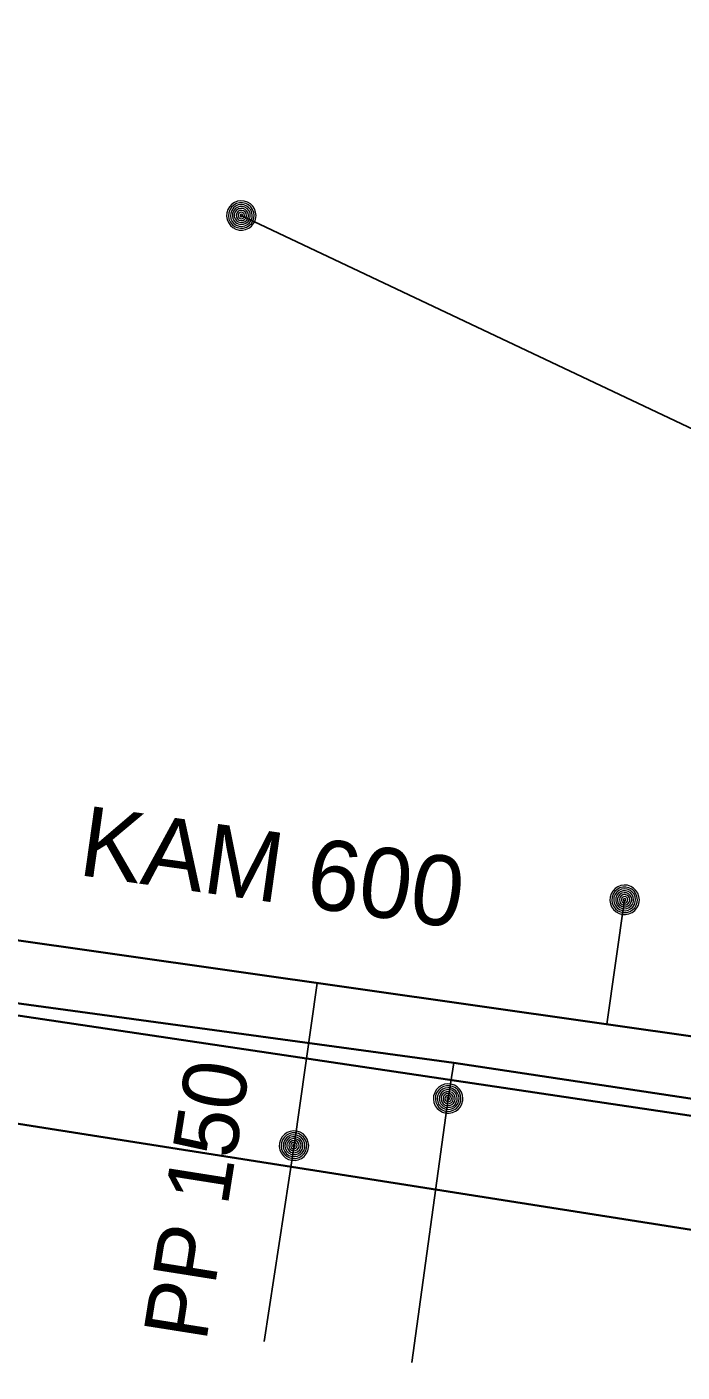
# Model space of a CAD drawing. Extents: x -866761 to -866592, y -1013996 to -1013877.
# Drawn here: x -866639.65 to -866629.36, y -1013979.36 to -1013958.25 of the extents above; entities that cross this region are included whole.
import ezdxf

# ---------------------------------------------------------------- set-up
doc = ezdxf.new("R2010")
doc.units = 0
doc.header["$LTSCALE"] = 0.44
for name, color, linetype, lineweight in [('1', 7, 'Continuous', 35), ('12', 7, 'Continuous', 13), ('21', 7, 'Continuous', 35), ('23', 7, 'Continuous', 25), ('25', 7, 'Continuous', 13), ('3', 7, 'Continuous', 25), ('32', 7, 'Continuous', 13)]:
    doc.layers.add(name, color=color, linetype=linetype, lineweight=lineweight)

msp = doc.modelspace()

# ---------------------------------------------------------------- linework, layer by layer
at = {"layer": '1'}
msp.add_line((-866612.967, -1013977.763), (-866734.931, -1013959.586), dxfattribs=at)
for points in [[(-866612.815, -1013977.108), (-866621.035, -1013976.325), (-866621.378, -1013976.297), (-866626.243, -1013975.519), (-866632.94, -1013974.51), (-866645.03, -1013972.86), (-866647.305, -1013972.501), (-866654.48, -1013971.31), (-866668.882, -1013969.171), (-866678.229, -1013967.78), (-866685.446, -1013966.718), (-866689.8, -1013966.06), (-866697.865, -1013964.927), (-866723.097, -1013961.352), (-866726.923, -1013960.77), (-866727.214, -1013960.734), (-866737.38, -1013959.64), (-866746.09, -1013958.48), (-866747.84, -1013958.25), (-866748.13, -1013958.99), (-866750.15, -1013958.69)], [(-866613.338, -1013979.363), (-866624.951, -1013977.802), (-866715.256, -1013963.593), (-866735.102, -1013960.577)]]:
    msp.add_lwpolyline(points, dxfattribs=at)
at = {"layer": '12'}
for points in [[(-866632.799, -1013975.07), (-866632.805, -1013975.018), (-866632.822, -1013974.968), (-866632.851, -1013974.924), (-866632.888, -1013974.887), (-866632.933, -1013974.86), (-866632.983, -1013974.843), (-866633.036, -1013974.839), (-866633.088, -1013974.846), (-866633.137, -1013974.865), (-866633.18, -1013974.894), (-866633.216, -1013974.933), (-866633.242, -1013974.978), (-866633.258, -1013975.029), (-866633.261, -1013975.081), (-866633.253, -1013975.133), (-866633.233, -1013975.182), (-866633.202, -1013975.225), (-866633.163, -1013975.259), (-866633.117, -1013975.285), (-866633.066, -1013975.299), (-866633.013, -1013975.301), (-866632.962, -1013975.291), (-866632.914, -1013975.27), (-866632.871, -1013975.239), (-866632.837, -1013975.198), (-866632.813, -1013975.152), (-866632.801, -1013975.101)], [(-866632.829, -1013975.07), (-866632.835, -1013975.021), (-866632.852, -1013974.975), (-866632.88, -1013974.935), (-866632.917, -1013974.903), (-866632.961, -1013974.881), (-866633.009, -1013974.87), (-866633.058, -1013974.87), (-866633.105, -1013974.883), (-866633.148, -1013974.907), (-866633.184, -1013974.94), (-866633.211, -1013974.981), (-866633.227, -1013975.028), (-866633.231, -1013975.077), (-866633.224, -1013975.125), (-866633.205, -1013975.17), (-866633.175, -1013975.21), (-866633.137, -1013975.241), (-866633.093, -1013975.261), (-866633.045, -1013975.271), (-866632.996, -1013975.269), (-866632.949, -1013975.254), (-866632.906, -1013975.229), (-866632.872, -1013975.195), (-866632.846, -1013975.153), (-866632.832, -1013975.106)], [(-866632.859, -1013975.07), (-866632.865, -1013975.025), (-866632.882, -1013974.983), (-866632.91, -1013974.948), (-866632.946, -1013974.921), (-866632.988, -1013974.904), (-866633.033, -1013974.899), (-866633.078, -1013974.905), (-866633.119, -1013974.924), (-866633.154, -1013974.952), (-866633.181, -1013974.989), (-866633.197, -1013975.031), (-866633.201, -1013975.076), (-866633.194, -1013975.121), (-866633.175, -1013975.162), (-866633.146, -1013975.196), (-866633.109, -1013975.222), (-866633.066, -1013975.238), (-866633.021, -1013975.241), (-866632.976, -1013975.233), (-866632.936, -1013975.213), (-866632.902, -1013975.184), (-866632.876, -1013975.146), (-866632.862, -1013975.103)], [(-866632.889, -1013975.07), (-866632.894, -1013975.029), (-866632.912, -1013974.992), (-866632.939, -1013974.961), (-866632.974, -1013974.94), (-866633.014, -1013974.929), (-866633.055, -1013974.931), (-866633.094, -1013974.944), (-866633.128, -1013974.968), (-866633.153, -1013975), (-866633.168, -1013975.038), (-866633.171, -1013975.079), (-866633.163, -1013975.119), (-866633.143, -1013975.155), (-866633.114, -1013975.184), (-866633.077, -1013975.203), (-866633.037, -1013975.211), (-866632.996, -1013975.207), (-866632.958, -1013975.192), (-866632.926, -1013975.166), (-866632.903, -1013975.132), (-866632.89, -1013975.093)], [(-866632.919, -1013975.07), (-866632.924, -1013975.034), (-866632.942, -1013975.002), (-866632.968, -1013974.977), (-866633.002, -1013974.962), (-866633.038, -1013974.959), (-866633.073, -1013974.967), (-866633.104, -1013974.987), (-866633.127, -1013975.015), (-866633.14, -1013975.049), (-866633.14, -1013975.086), (-866633.129, -1013975.121), (-866633.108, -1013975.15), (-866633.078, -1013975.171), (-866633.043, -1013975.181), (-866633.006, -1013975.179), (-866632.972, -1013975.165), (-866632.945, -1013975.142), (-866632.926, -1013975.11), (-866632.919, -1013975.075)], [(-866632.949, -1013975.07), (-866632.954, -1013975.039), (-866632.971, -1013975.013), (-866632.997, -1013974.996), (-866633.027, -1013974.989), (-866633.058, -1013974.993), (-866633.085, -1013975.01), (-866633.103, -1013975.034), (-866633.111, -1013975.065), (-866633.107, -1013975.095), (-866633.092, -1013975.123), (-866633.068, -1013975.142), (-866633.038, -1013975.151), (-866633.007, -1013975.148), (-866632.979, -1013975.134), (-866632.959, -1013975.11), (-866632.949, -1013975.081)], [(-866632.979, -1013975.07), (-866632.984, -1013975.046), (-866633.001, -1013975.028), (-866633.024, -1013975.019), (-866633.048, -1013975.022), (-866633.069, -1013975.036), (-866633.08, -1013975.058), (-866633.08, -1013975.083), (-866633.068, -1013975.104), (-866633.048, -1013975.118), (-866633.023, -1013975.121), (-866633, -1013975.112), (-866632.984, -1013975.094)], [(-866633.009, -1013975.07), (-866633.014, -1013975.055), (-866633.029, -1013975.049), (-866633.044, -1013975.053), (-866633.051, -1013975.067), (-866633.047, -1013975.082), (-866633.034, -1013975.091), (-866633.019, -1013975.088), (-866633.009, -1013975.076)]]:
    msp.add_lwpolyline(points, close=True, dxfattribs=at)
at = {"layer": '21'}
msp.add_line((-866647.459, -1013971.5), (-866622.959, -1013974.98), dxfattribs=at)
at = {"layer": '23'}
for p, q in [((-866636.279, -1013961.21), (-866624.162, -1013966.944)), ((-866630.538, -1013973.904), (-866630.259, -1013971.95))]:
    msp.add_line(p, q, dxfattribs=at)
msp.add_lwpolyline([(-866635.087, -1013973.257), (-866635.449, -1013975.804), (-866635.918, -1013978.885)], dxfattribs=at)
at = {"layer": '25'}
for points in [[(-866636.048, -1013961.21), (-866636.054, -1013961.158), (-866636.071, -1013961.108), (-866636.1, -1013961.064), (-866636.137, -1013961.027), (-866636.182, -1013961), (-866636.232, -1013960.983), (-866636.285, -1013960.979), (-866636.337, -1013960.986), (-866636.386, -1013961.005), (-866636.429, -1013961.034), (-866636.465, -1013961.073), (-866636.491, -1013961.118), (-866636.507, -1013961.169), (-866636.51, -1013961.221), (-866636.502, -1013961.273), (-866636.482, -1013961.322), (-866636.451, -1013961.365), (-866636.412, -1013961.399), (-866636.366, -1013961.425), (-866636.315, -1013961.439), (-866636.262, -1013961.441), (-866636.211, -1013961.431), (-866636.163, -1013961.41), (-866636.12, -1013961.379), (-866636.086, -1013961.338), (-866636.062, -1013961.292), (-866636.049, -1013961.241)], [(-866636.078, -1013961.21), (-866636.084, -1013961.161), (-866636.101, -1013961.115), (-866636.129, -1013961.075), (-866636.166, -1013961.043), (-866636.21, -1013961.021), (-866636.258, -1013961.01), (-866636.307, -1013961.01), (-866636.353, -1013961.023), (-866636.397, -1013961.047), (-866636.433, -1013961.08), (-866636.46, -1013961.121), (-866636.476, -1013961.168), (-866636.48, -1013961.217), (-866636.473, -1013961.265), (-866636.454, -1013961.31), (-866636.424, -1013961.35), (-866636.386, -1013961.381), (-866636.342, -1013961.401), (-866636.294, -1013961.411), (-866636.245, -1013961.409), (-866636.198, -1013961.394), (-866636.155, -1013961.369), (-866636.12, -1013961.335), (-866636.095, -1013961.293), (-866636.081, -1013961.246)], [(-866636.108, -1013961.21), (-866636.114, -1013961.165), (-866636.13, -1013961.123), (-866636.159, -1013961.088), (-866636.195, -1013961.061), (-866636.237, -1013961.044), (-866636.282, -1013961.039), (-866636.326, -1013961.045), (-866636.368, -1013961.064), (-866636.402, -1013961.092), (-866636.429, -1013961.129), (-866636.446, -1013961.171), (-866636.45, -1013961.216), (-866636.443, -1013961.261), (-866636.424, -1013961.302), (-866636.395, -1013961.336), (-866636.358, -1013961.362), (-866636.315, -1013961.378), (-866636.27, -1013961.381), (-866636.225, -1013961.373), (-866636.184, -1013961.353), (-866636.151, -1013961.324), (-866636.125, -1013961.286), (-866636.111, -1013961.243)], [(-866636.138, -1013961.21), (-866636.142, -1013961.169), (-866636.161, -1013961.132), (-866636.188, -1013961.101), (-866636.223, -1013961.08), (-866636.263, -1013961.069), (-866636.304, -1013961.071), (-866636.343, -1013961.084), (-866636.377, -1013961.108), (-866636.402, -1013961.14), (-866636.417, -1013961.178), (-866636.419, -1013961.219), (-866636.412, -1013961.259), (-866636.392, -1013961.295), (-866636.363, -1013961.324), (-866636.326, -1013961.343), (-866636.286, -1013961.351), (-866636.245, -1013961.347), (-866636.206, -1013961.332), (-866636.174, -1013961.306), (-866636.152, -1013961.272), (-866636.139, -1013961.233)], [(-866636.168, -1013961.21), (-866636.173, -1013961.174), (-866636.191, -1013961.142), (-866636.217, -1013961.117), (-866636.25, -1013961.102), (-866636.287, -1013961.099), (-866636.321, -1013961.107), (-866636.353, -1013961.127), (-866636.375, -1013961.155), (-866636.389, -1013961.189), (-866636.389, -1013961.226), (-866636.378, -1013961.261), (-866636.357, -1013961.29), (-866636.326, -1013961.311), (-866636.292, -1013961.321), (-866636.255, -1013961.319), (-866636.221, -1013961.305), (-866636.194, -1013961.282), (-866636.174, -1013961.25), (-866636.168, -1013961.215)], [(-866636.198, -1013961.21), (-866636.203, -1013961.179), (-866636.22, -1013961.153), (-866636.245, -1013961.136), (-866636.276, -1013961.129), (-866636.307, -1013961.133), (-866636.334, -1013961.15), (-866636.352, -1013961.174), (-866636.36, -1013961.205), (-866636.356, -1013961.235), (-866636.341, -1013961.263), (-866636.316, -1013961.282), (-866636.287, -1013961.291), (-866636.255, -1013961.288), (-866636.228, -1013961.274), (-866636.208, -1013961.25), (-866636.198, -1013961.221)], [(-866636.228, -1013961.21), (-866636.233, -1013961.186), (-866636.25, -1013961.168), (-866636.272, -1013961.159), (-866636.297, -1013961.162), (-866636.318, -1013961.176), (-866636.329, -1013961.198), (-866636.329, -1013961.223), (-866636.316, -1013961.244), (-866636.297, -1013961.258), (-866636.272, -1013961.261), (-866636.249, -1013961.252), (-866636.233, -1013961.234)], [(-866636.258, -1013961.21), (-866636.263, -1013961.195), (-866636.277, -1013961.189), (-866636.293, -1013961.193), (-866636.299, -1013961.207), (-866636.296, -1013961.222), (-866636.282, -1013961.231), (-866636.267, -1013961.228), (-866636.258, -1013961.216)], [(-866630.027, -1013971.95), (-866630.034, -1013971.898), (-866630.051, -1013971.848), (-866630.08, -1013971.804), (-866630.117, -1013971.767), (-866630.162, -1013971.74), (-866630.212, -1013971.723), (-866630.265, -1013971.719), (-866630.316, -1013971.726), (-866630.365, -1013971.745), (-866630.409, -1013971.774), (-866630.445, -1013971.813), (-866630.471, -1013971.858), (-866630.487, -1013971.909), (-866630.49, -1013971.961), (-866630.482, -1013972.013), (-866630.462, -1013972.062), (-866630.431, -1013972.105), (-866630.392, -1013972.139), (-866630.346, -1013972.165), (-866630.294, -1013972.179), (-866630.242, -1013972.181), (-866630.191, -1013972.171), (-866630.142, -1013972.15), (-866630.1, -1013972.119), (-866630.066, -1013972.078), (-866630.042, -1013972.032), (-866630.029, -1013971.981)], [(-866630.058, -1013971.95), (-866630.064, -1013971.901), (-866630.081, -1013971.855), (-866630.108, -1013971.815), (-866630.146, -1013971.783), (-866630.19, -1013971.761), (-866630.238, -1013971.75), (-866630.287, -1013971.75), (-866630.333, -1013971.763), (-866630.377, -1013971.787), (-866630.413, -1013971.82), (-866630.44, -1013971.861), (-866630.456, -1013971.908), (-866630.46, -1013971.957), (-866630.453, -1013972.005), (-866630.434, -1013972.05), (-866630.404, -1013972.09), (-866630.365, -1013972.121), (-866630.321, -1013972.141), (-866630.274, -1013972.151), (-866630.225, -1013972.149), (-866630.178, -1013972.134), (-866630.135, -1013972.109), (-866630.1, -1013972.075), (-866630.075, -1013972.033), (-866630.061, -1013971.986)], [(-866630.088, -1013971.95), (-866630.093, -1013971.905), (-866630.11, -1013971.863), (-866630.139, -1013971.828), (-866630.174, -1013971.801), (-866630.217, -1013971.784), (-866630.262, -1013971.779), (-866630.306, -1013971.785), (-866630.348, -1013971.804), (-866630.382, -1013971.832), (-866630.409, -1013971.869), (-866630.426, -1013971.911), (-866630.429, -1013971.956), (-866630.423, -1013972.001), (-866630.404, -1013972.042), (-866630.375, -1013972.076), (-866630.338, -1013972.102), (-866630.294, -1013972.118), (-866630.25, -1013972.121), (-866630.205, -1013972.113), (-866630.164, -1013972.093), (-866630.13, -1013972.064), (-866630.105, -1013972.026), (-866630.091, -1013971.983)], [(-866630.118, -1013971.95), (-866630.122, -1013971.909), (-866630.141, -1013971.872), (-866630.168, -1013971.841), (-866630.203, -1013971.82), (-866630.243, -1013971.809), (-866630.284, -1013971.811), (-866630.323, -1013971.824), (-866630.357, -1013971.848), (-866630.382, -1013971.88), (-866630.397, -1013971.918), (-866630.399, -1013971.959), (-866630.392, -1013971.999), (-866630.372, -1013972.035), (-866630.343, -1013972.064), (-866630.306, -1013972.083), (-866630.266, -1013972.091), (-866630.225, -1013972.087), (-866630.186, -1013972.072), (-866630.154, -1013972.046), (-866630.132, -1013972.012), (-866630.119, -1013971.973)], [(-866630.147, -1013971.95), (-866630.152, -1013971.914), (-866630.171, -1013971.882), (-866630.196, -1013971.857), (-866630.23, -1013971.842), (-866630.267, -1013971.839), (-866630.301, -1013971.847), (-866630.333, -1013971.867), (-866630.355, -1013971.895), (-866630.369, -1013971.929), (-866630.369, -1013971.966), (-866630.358, -1013972.001), (-866630.337, -1013972.03), (-866630.306, -1013972.051), (-866630.272, -1013972.061), (-866630.235, -1013972.059), (-866630.201, -1013972.045), (-866630.174, -1013972.022), (-866630.154, -1013971.99), (-866630.147, -1013971.955)], [(-866630.178, -1013971.95), (-866630.183, -1013971.919), (-866630.2, -1013971.893), (-866630.225, -1013971.876), (-866630.255, -1013971.869), (-866630.287, -1013971.873), (-866630.314, -1013971.89), (-866630.331, -1013971.914), (-866630.34, -1013971.945), (-866630.336, -1013971.975), (-866630.321, -1013972.003), (-866630.296, -1013972.022), (-866630.267, -1013972.031), (-866630.235, -1013972.028), (-866630.208, -1013972.014), (-866630.188, -1013971.99), (-866630.178, -1013971.961)], [(-866630.208, -1013971.95), (-866630.213, -1013971.926), (-866630.23, -1013971.908), (-866630.252, -1013971.899), (-866630.277, -1013971.902), (-866630.298, -1013971.916), (-866630.309, -1013971.938), (-866630.309, -1013971.963), (-866630.296, -1013971.984), (-866630.277, -1013971.998), (-866630.252, -1013972.001), (-866630.228, -1013971.992), (-866630.213, -1013971.974)], [(-866630.238, -1013971.95), (-866630.243, -1013971.935), (-866630.257, -1013971.929), (-866630.272, -1013971.933), (-866630.279, -1013971.947), (-866630.276, -1013971.962), (-866630.262, -1013971.971), (-866630.247, -1013971.968), (-866630.238, -1013971.956)]]:
    msp.add_lwpolyline(points, close=True, dxfattribs=at)
at = {"layer": '3'}
msp.add_lwpolyline([(-866632.94, -1013974.51), (-866633.03, -1013975.07), (-866633.599, -1013979.21)], dxfattribs=at)
at = {"layer": '32'}
for points in [[(-866635.221, -1013975.809), (-866635.227, -1013975.757), (-866635.244, -1013975.707), (-866635.273, -1013975.663), (-866635.31, -1013975.626), (-866635.355, -1013975.599), (-866635.405, -1013975.582), (-866635.458, -1013975.578), (-866635.51, -1013975.585), (-866635.559, -1013975.604), (-866635.602, -1013975.633), (-866635.638, -1013975.672), (-866635.664, -1013975.717), (-866635.68, -1013975.768), (-866635.683, -1013975.82), (-866635.675, -1013975.872), (-866635.655, -1013975.921), (-866635.624, -1013975.964), (-866635.585, -1013975.998), (-866635.539, -1013976.024), (-866635.488, -1013976.038), (-866635.435, -1013976.04), (-866635.384, -1013976.03), (-866635.336, -1013976.009), (-866635.293, -1013975.978), (-866635.259, -1013975.937), (-866635.235, -1013975.891), (-866635.223, -1013975.84)], [(-866635.251, -1013975.809), (-866635.257, -1013975.76), (-866635.274, -1013975.714), (-866635.302, -1013975.674), (-866635.339, -1013975.642), (-866635.383, -1013975.62), (-866635.431, -1013975.609), (-866635.48, -1013975.609), (-866635.527, -1013975.622), (-866635.57, -1013975.646), (-866635.606, -1013975.679), (-866635.633, -1013975.72), (-866635.649, -1013975.767), (-866635.653, -1013975.816), (-866635.646, -1013975.864), (-866635.627, -1013975.909), (-866635.597, -1013975.949), (-866635.559, -1013975.98), (-866635.515, -1013976), (-866635.467, -1013976.01), (-866635.418, -1013976.008), (-866635.371, -1013975.993), (-866635.328, -1013975.968), (-866635.294, -1013975.934), (-866635.268, -1013975.892), (-866635.254, -1013975.845)], [(-866635.281, -1013975.809), (-866635.287, -1013975.764), (-866635.304, -1013975.722), (-866635.332, -1013975.687), (-866635.368, -1013975.66), (-866635.41, -1013975.643), (-866635.455, -1013975.638), (-866635.5, -1013975.644), (-866635.541, -1013975.663), (-866635.576, -1013975.691), (-866635.603, -1013975.728), (-866635.619, -1013975.77), (-866635.623, -1013975.815), (-866635.616, -1013975.86), (-866635.597, -1013975.901), (-866635.568, -1013975.935), (-866635.531, -1013975.961), (-866635.488, -1013975.977), (-866635.443, -1013975.98), (-866635.398, -1013975.972), (-866635.358, -1013975.952), (-866635.324, -1013975.923), (-866635.298, -1013975.885), (-866635.284, -1013975.842)], [(-866635.311, -1013975.809), (-866635.316, -1013975.768), (-866635.334, -1013975.731), (-866635.361, -1013975.7), (-866635.396, -1013975.679), (-866635.436, -1013975.668), (-866635.477, -1013975.67), (-866635.516, -1013975.683), (-866635.55, -1013975.707), (-866635.575, -1013975.739), (-866635.59, -1013975.777), (-866635.593, -1013975.818), (-866635.585, -1013975.858), (-866635.565, -1013975.894), (-866635.536, -1013975.923), (-866635.499, -1013975.942), (-866635.459, -1013975.95), (-866635.418, -1013975.946), (-866635.38, -1013975.931), (-866635.348, -1013975.905), (-866635.325, -1013975.871), (-866635.312, -1013975.832)], [(-866635.341, -1013975.809), (-866635.346, -1013975.773), (-866635.364, -1013975.741), (-866635.39, -1013975.716), (-866635.424, -1013975.701), (-866635.46, -1013975.698), (-866635.495, -1013975.706), (-866635.526, -1013975.726), (-866635.549, -1013975.754), (-866635.562, -1013975.788), (-866635.562, -1013975.825), (-866635.551, -1013975.86), (-866635.53, -1013975.889), (-866635.5, -1013975.91), (-866635.465, -1013975.92), (-866635.428, -1013975.918), (-866635.394, -1013975.904), (-866635.367, -1013975.881), (-866635.348, -1013975.849), (-866635.341, -1013975.814)], [(-866635.371, -1013975.809), (-866635.376, -1013975.778), (-866635.393, -1013975.752), (-866635.419, -1013975.735), (-866635.449, -1013975.728), (-866635.48, -1013975.732), (-866635.507, -1013975.749), (-866635.525, -1013975.773), (-866635.533, -1013975.804), (-866635.529, -1013975.834), (-866635.514, -1013975.862), (-866635.49, -1013975.881), (-866635.46, -1013975.89), (-866635.429, -1013975.887), (-866635.401, -1013975.873), (-866635.381, -1013975.849), (-866635.371, -1013975.82)], [(-866635.401, -1013975.809), (-866635.406, -1013975.785), (-866635.423, -1013975.767), (-866635.446, -1013975.758), (-866635.47, -1013975.761), (-866635.491, -1013975.775), (-866635.502, -1013975.797), (-866635.502, -1013975.822), (-866635.49, -1013975.843), (-866635.47, -1013975.857), (-866635.445, -1013975.86), (-866635.422, -1013975.851), (-866635.406, -1013975.833)], [(-866635.431, -1013975.809), (-866635.436, -1013975.794), (-866635.451, -1013975.788), (-866635.466, -1013975.792), (-866635.473, -1013975.806), (-866635.469, -1013975.821), (-866635.456, -1013975.83), (-866635.441, -1013975.827), (-866635.431, -1013975.815)]]:
    msp.add_lwpolyline(points, close=True, dxfattribs=at)

# ---------------------------------------------------------------- texts
at = {"layer": '1'}
msp.add_text('KAM 600 ', height=1.1, rotation=352, dxfattribs=at).set_placement((-866638.859, -1013971.559))
at = {"layer": '23'}
msp.add_text('PP 150', height=1, rotation=81, dxfattribs=at).set_placement((-866636.832, -1013978.901))

doc.saveas('drawing.dxf')
